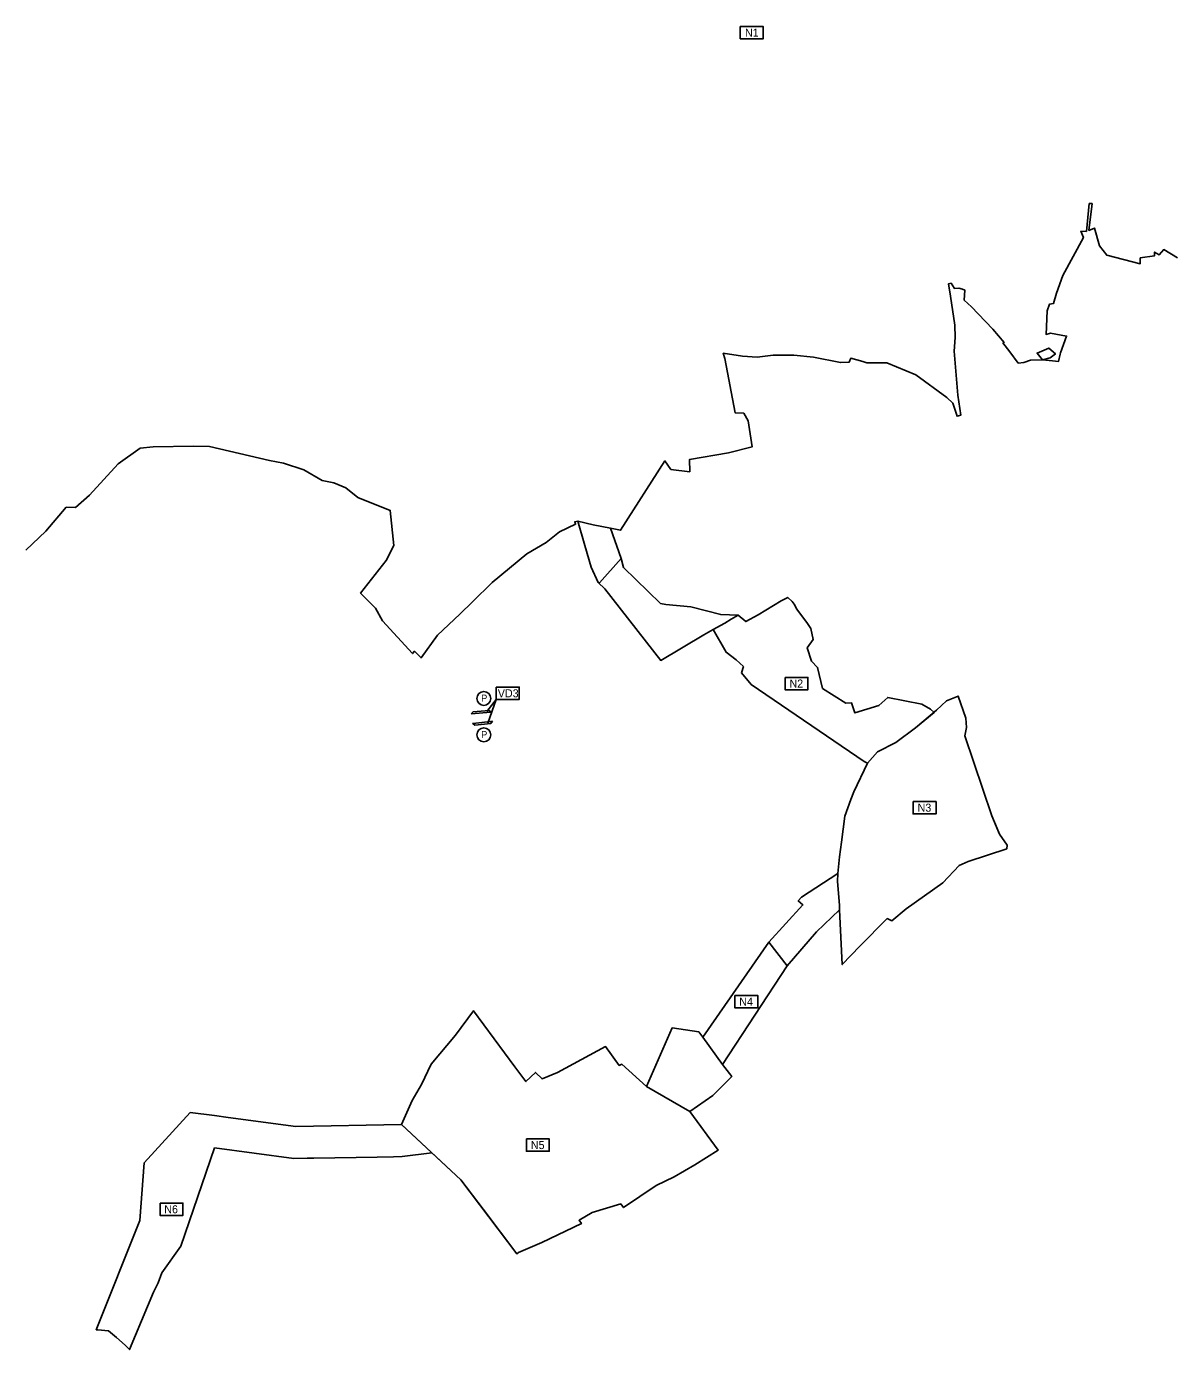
# Model space of a CAD drawing. Extents: x -547623 to -530360, y -1095798 to -1086523.
# Drawn here: x -546194 to -544764, y -1095798 to -1094145 of the extents above; entities that cross this region are included whole.
import ezdxf

# ---------------------------------------------------------------- set-up
doc = ezdxf.new("R2010")
doc.units = 0
for name, color, linetype in [('Vrstva 2', 7, 'Continuous'), ('Vrstva 27', 7, 'Continuous'), ('Vrstva 28', 7, 'Continuous'), ('Vrstva 29', 7, 'Continuous'), ('Vrstva 32', 7, 'Continuous'), ('Vrstva 36', 7, 'Continuous'), ('Vrstva 73', 7, 'Continuous')]:
    doc.layers.add(name, color=color, linetype=linetype)

msp = doc.modelspace()

# ---------------------------------------------------------------- linework, layer by layer
at = {"layer": 'Vrstva 2'}
for q in [(-545618.4, -1095001), (-545617.1, -1095015.3)]:
    msp.add_line((-545606.7, -1094985.8), q, dxfattribs=at)
msp.add_lwpolyline([(-545606.7, -1094970.3), (-545578, -1094970.3), (-545578, -1094985.8), (-545606.7, -1094985.8)], close=True, dxfattribs=at)
at = {"layer": 'Vrstva 27'}
msp.add_lwpolyline([(-546194.3, -1094799.4), (-546169.5, -1094775.5), (-546144.1, -1094745.5), (-546132.4, -1094746.2), (-546115, -1094730.6), (-546079, -1094691.6), (-546051.5, -1094672), (-546035.4, -1094670.2), (-545984.8, -1094669.3), (-545965, -1094669.6), (-545889.9, -1094687.2), (-545872.5, -1094690.6), (-545847.3, -1094699.1), (-545824.3, -1094712.4), (-545809.7, -1094715.1), (-545794.8, -1094721.6), (-545779.8, -1094733.3), (-545739.1, -1094749.6), (-545734.6, -1094793.4), (-545744.1, -1094812.1), (-545776.1, -1094853.2), (-545757.5, -1094871.9), (-545748.7, -1094887.7), (-545711.5, -1094928.4), (-545708.9, -1094925.6), (-545700.5, -1094933.9), (-545680, -1094905.5), (-545652, -1094879.2), (-545636.5, -1094863.8), (-545611.7, -1094839.5), (-545568.6, -1094803.9), (-545544.4, -1094789.6), (-545527.8, -1094776.3), (-545507.6, -1094767), (-545508.6, -1094763.8), (-545504.7, -1094763), (-545485.5, -1094767.6), (-545463.9, -1094771.9), (-545451.2, -1094774.5), (-545395.9, -1094687.7), (-545388.4, -1094698.5), (-545364.8, -1094701.3), (-545365.1, -1094686), (-545316.5, -1094677.8), (-545286.7, -1094670.1), (-545291.7, -1094637.6), (-545297.3, -1094628.1), (-545308, -1094627.9), (-545321.1, -1094559.7), (-545322.9, -1094553.3), (-545298.8, -1094556.8), (-545280.4, -1094558.3), (-545260.8, -1094555.6), (-545234.9, -1094555.8), (-545210.4, -1094558.2), (-545176.6, -1094564.9), (-545165.6, -1094564.3), (-545163.6, -1094559.6), (-545148.6, -1094563.8), (-545143.4, -1094565.3), (-545118.4, -1094565.3), (-545082.5, -1094580.4), (-545043.5, -1094608.6), (-545036, -1094615.7), (-545030.7, -1094631.9), (-545026.2, -1094630.6), (-545030, -1094605.6), (-545034.6, -1094550.8), (-545033.3, -1094533.8), (-545033.5, -1094518.2), (-545039.1, -1094481.9), (-545041.3, -1094466.5), (-545038.3, -1094465.8), (-545034.1, -1094472.3), (-545028.6, -1094471.9), (-545024, -1094473.4), (-545021.1, -1094474.4), (-545021.8, -1094486.9), (-545012.8, -1094495.3), (-545004.3, -1094504.2), (-544986, -1094523.4), (-544972.1, -1094540), (-544973.6, -1094540.4), (-544964.9, -1094551.6), (-544954.3, -1094565.5), (-544947.3, -1094564.8), (-544938.9, -1094561.8), (-544924, -1094561.5), (-544930.9, -1094553.1), (-544916.2, -1094546.8), (-544908, -1094554.2), (-544914.3, -1094559.1), (-544924, -1094561.5), (-544911.7, -1094562.9), (-544904.2, -1094563.7), (-544902.1, -1094554.5), (-544901.5, -1094552.6), (-544893.9, -1094531.9), (-544913.9, -1094528.3), (-544919.6, -1094529.8), (-544918.4, -1094500.1), (-544915.1, -1094491.9), (-544910.3, -1094491.2), (-544906.4, -1094478.3), (-544898.7, -1094456.2), (-544873, -1094408.8), (-544876.1, -1094400.8), (-544869.2, -1094401.1), (-544865.7, -1094366.4), (-544862, -1094366.4), (-544866.1, -1094399.8), (-544859.1, -1094397), (-544853, -1094418.9), (-544843.8, -1094430.8), (-544801.9, -1094441.4), (-544801.8, -1094434.1), (-544784.2, -1094431.6), (-544783.9, -1094426.9), (-544778.4, -1094430.5), (-544772.6, -1094423.7), (-544755.4, -1094434.1)], dxfattribs=at)
at = {"layer": 'Vrstva 28'}
for p, q in [((-545958.7, -1095505.7), (-545989, -1095501.7)), ((-546052, -1095636.9), (-546106.6, -1095773.3)), ((-546024.4, -1095702.2), (-546000.8, -1095668.6)), ((-546029, -1095714.5), (-546024.4, -1095702.2)), ((-546035, -1095726.3), (-546029, -1095714.5))]:
    msp.add_line(p, q, dxfattribs=at)
for points in [[(-545485.5, -1094767.6), (-545504.7, -1094763), (-545496, -1094793.4), (-545488.2, -1094820.5), (-545479.4, -1094839.5)], [(-545450.7, -1094809.9), (-545463.9, -1094771.9), (-545485.5, -1094767.6)], [(-545304.5, -1094880.5), (-545326.2, -1094879.8), (-545363.5, -1094870.2), (-545394.6, -1094867.1), (-545401.5, -1094865.8), (-545447.7, -1094820.9), (-545450.7, -1094809.9)], [(-545479.4, -1094839.5), (-545471.1, -1094847.8), (-545401.1, -1094937.1), (-545347.4, -1094905.2), (-545335.4, -1094898.4)], [(-545335.4, -1094898.4), (-545319.4, -1094926.9), (-545307, -1094936.2), (-545297.8, -1094944.6), (-545300.1, -1094952.7), (-545288, -1094967.2), (-545146.7, -1095063.3), (-545142.8, -1095065.2), (-545136.3, -1095058.2), (-545130.2, -1095051.2), (-545107.3, -1095039.6), (-545082.9, -1095021.3), (-545059.6, -1095001.9), (-545064, -1094997.8), (-545074.9, -1094991.6), (-545117.4, -1094983.3), (-545128.4, -1094993.3), (-545158.4, -1095002.7), (-545162.6, -1094990.2), (-545169.8, -1094990.4), (-545198.8, -1094972.1), (-545205.2, -1094945.7), (-545212.7, -1094937.8), (-545218.2, -1094921.3), (-545210.7, -1094910.9), (-545213.4, -1094897.3), (-545217.9, -1094891), (-545231, -1094872.8), (-545234.5, -1094866.7), (-545236.8, -1094863.5), (-545242.3, -1094858.3), (-545250.8, -1094862.5), (-545279.4, -1094880.1), (-545294.7, -1094888.6), (-545304.5, -1094880.5)], [(-545243.2, -1095318.4), (-545206.5, -1095275.9), (-545177.7, -1095248.6), (-545177.8, -1095242.9), (-545180.4, -1095213.2), (-545179.7, -1095203.4), (-545225.3, -1095232.6), (-545229.3, -1095237.4), (-545223.5, -1095242.4), (-545265.9, -1095289.1)], [(-545265.9, -1095289.1), (-545348.7, -1095407.7)], [(-545324, -1095441.7), (-545243.2, -1095318.4)], [(-545348.7, -1095407.7), (-545353.6, -1095400.9), (-545386.7, -1095396), (-545418.8, -1095469.4), (-545364.9, -1095500.4), (-545336.2, -1095480.7), (-545312.4, -1095457), (-545324, -1095441.7)], [(-545989, -1095501.7), (-546046.7, -1095564.7), (-546052, -1095636.9)], [(-545941.5, -1095508), (-545958.7, -1095505.7)], [(-545725, -1095516.9), (-545857.1, -1095519.2), (-545941.5, -1095508)], [(-545734.9, -1095557.1), (-545724.3, -1095556.9), (-545687.2, -1095552), (-545725, -1095516.9)], [(-546000.8, -1095668.6), (-545958.7, -1095546.1)], [(-545958.7, -1095546.1), (-545859.4, -1095559.2), (-545842.8, -1095558.9), (-545834.7, -1095558.8), (-545755.5, -1095557.4)], [(-545755.5, -1095557.4), (-545734.9, -1095557.1)], [(-546106.6, -1095773.3), (-546104.7, -1095773.2), (-546091.3, -1095774.5), (-546081.4, -1095783), (-546070.4, -1095792.5), (-546064.8, -1095797.9), (-546035, -1095726.3)]]:
    msp.add_lwpolyline(points, dxfattribs=at)
at = {"layer": 'Vrstva 29'}
for points in [[(-545637.8, -1095003.7), (-545613.4, -1095001.6), (-545613.1, -1095001.6), (-545615.7, -1094999.4), (-545635.6, -1095001.2), (-545637.8, -1095003.7)], [(-545611.3, -1095013.1), (-545613.8, -1095013.4), (-545636.1, -1095015.8), (-545633.4, -1095018.1), (-545613.5, -1095015.9), (-545611.3, -1095013.1)]]:
    msp.add_lwpolyline(points, dxfattribs=at)
for centre in [(-545622.2, -1094984.5), (-545622.2, -1095029.9)]:
    msp.add_circle(centre, 8.68, dxfattribs=at)
at = {"layer": 'Vrstva 32'}
for points in [[(-545016.9, -1095188.3), (-544968.8, -1095172.4), (-544968.4, -1095167.9), (-544977.6, -1095154), (-544987.5, -1095131.1), (-545021.1, -1095031.3), (-545019.2, -1095020.9), (-545019.9, -1095009.1), (-545029.6, -1094981.6), (-545043.9, -1094987.4), (-545056.3, -1094999.1), (-545082.9, -1095021.3), (-545107.3, -1095039.6), (-545130.2, -1095051.2), (-545136.3, -1095058.2), (-545142.8, -1095065.2), (-545159.6, -1095101.2), (-545163.6, -1095110.7), (-545171.2, -1095131.7), (-545175.2, -1095164.2), (-545177.8, -1095182.3), (-545179.7, -1095203.4), (-545180.4, -1095213.2), (-545177.8, -1095242.9), (-545177.7, -1095248.6), (-545174.3, -1095317.1), (-545152.4, -1095294.1), (-545118.3, -1095259.6), (-545112.3, -1095262.2), (-545094.5, -1095247.2), (-545048.7, -1095215), (-545028.2, -1095193.2), (-545016.9, -1095188.3)], [(-545569.5, -1095463.1), (-545583.4, -1095444.8), (-545635, -1095374.7), (-545657.5, -1095405.2), (-545687.8, -1095441.4), (-545700, -1095466.8), (-545711.6, -1095487), (-545725, -1095516.9)], [(-545329.2, -1095548.8), (-545364.9, -1095500.4), (-545418.8, -1095469.4), (-545449.8, -1095441.6), (-545453, -1095443), (-545470.1, -1095419.5), (-545530, -1095451.9), (-545549.3, -1095459.9), (-545557.6, -1095451.8), (-545569.5, -1095463.1)], [(-545725, -1095516.9), (-545650.8, -1095585.9), (-545580.8, -1095678.4), (-545578.7, -1095676.9), (-545549.5, -1095664.4), (-545500.2, -1095640.5), (-545503.2, -1095636.4), (-545487, -1095626.7), (-545451, -1095616.1)], [(-545451, -1095616.1), (-545447.6, -1095620.6), (-545406.9, -1095593), (-545384.2, -1095582.2), (-545358.6, -1095567.2), (-545329.2, -1095548.8)]]:
    msp.add_lwpolyline(points, dxfattribs=at)
at = {"layer": 'Vrstva 36'}
for points in [[(-545301.7, -1094145.1), (-545273.1, -1094145.1), (-545273.1, -1094160.5), (-545301.7, -1094160.5)], [(-545245.7, -1094958.2), (-545217.1, -1094958.2), (-545217.1, -1094973.7), (-545245.7, -1094973.7)], [(-545085.7, -1095113.3), (-545057.1, -1095113.3), (-545057.1, -1095128.7), (-545085.7, -1095128.7)], [(-545308.4, -1095355.6), (-545279.8, -1095355.6), (-545279.8, -1095371.1), (-545308.4, -1095371.1)], [(-545569, -1095534.8), (-545540.4, -1095534.8), (-545540.4, -1095550.2), (-545569, -1095550.2)], [(-546026.8, -1095614.9), (-545998.2, -1095614.9), (-545998.2, -1095630.4), (-546026.8, -1095630.4)]]:
    msp.add_lwpolyline(points, close=True, dxfattribs=at)
at = {"layer": 'Vrstva 73'}
for points in [[(-546194.3, -1094799.4), (-546169.5, -1094775.5), (-546144.1, -1094745.5), (-546132.4, -1094746.2), (-546115, -1094730.6), (-546079, -1094691.6), (-546051.5, -1094672), (-546035.4, -1094670.2), (-545984.8, -1094669.3), (-545965, -1094669.6), (-545889.9, -1094687.2), (-545872.5, -1094690.6), (-545847.3, -1094699.1), (-545824.3, -1094712.4), (-545809.7, -1094715.1), (-545794.8, -1094721.6), (-545779.8, -1094733.3), (-545739.1, -1094749.6), (-545734.6, -1094793.4), (-545744.1, -1094812.1), (-545776.1, -1094853.2), (-545757.5, -1094871.9), (-545748.7, -1094887.7), (-545711.5, -1094928.4), (-545708.9, -1094925.6), (-545700.5, -1094933.9), (-545680, -1094905.5), (-545652, -1094879.2), (-545636.5, -1094863.8), (-545611.7, -1094839.5), (-545568.6, -1094803.9), (-545544.4, -1094789.6), (-545527.8, -1094776.3), (-545507.6, -1094767), (-545508.6, -1094763.8), (-545504.7, -1094763), (-545485.5, -1094767.6), (-545463.9, -1094771.9), (-545451.2, -1094774.5), (-545395.9, -1094687.7), (-545388.4, -1094698.5), (-545364.8, -1094701.3), (-545365.1, -1094686), (-545316.5, -1094677.8), (-545286.7, -1094670.1), (-545291.7, -1094637.6), (-545297.3, -1094628.1), (-545308, -1094627.9), (-545321.1, -1094559.7), (-545322.9, -1094553.3), (-545298.8, -1094556.8), (-545280.4, -1094558.3), (-545260.8, -1094555.6), (-545234.9, -1094555.8), (-545210.4, -1094558.2), (-545176.6, -1094564.9), (-545165.6, -1094564.3), (-545163.6, -1094559.6), (-545148.6, -1094563.8), (-545143.4, -1094565.3), (-545118.4, -1094565.3), (-545082.5, -1094580.4), (-545043.5, -1094608.6), (-545036, -1094615.7), (-545030.7, -1094631.9), (-545026.2, -1094630.6), (-545030, -1094605.6), (-545034.6, -1094550.8), (-545033.3, -1094533.8), (-545033.5, -1094518.2), (-545039.1, -1094481.9), (-545041.3, -1094466.5), (-545038.3, -1094465.8), (-545034.1, -1094472.3), (-545028.6, -1094471.9), (-545024, -1094473.4), (-545021.1, -1094474.4), (-545021.8, -1094486.9), (-545012.8, -1094495.3), (-545004.3, -1094504.2), (-544986, -1094523.4), (-544972.1, -1094540), (-544973.6, -1094540.4), (-544964.9, -1094551.6), (-544954.3, -1094565.5), (-544947.3, -1094564.8), (-544938.9, -1094561.8), (-544924, -1094561.5), (-544930.9, -1094553.1), (-544916.2, -1094546.8), (-544908, -1094554.2), (-544914.3, -1094559.1), (-544924, -1094561.5), (-544911.7, -1094562.9), (-544904.2, -1094563.7), (-544902.1, -1094554.5), (-544901.5, -1094552.6), (-544893.9, -1094531.9), (-544913.9, -1094528.3), (-544919.6, -1094529.8), (-544918.4, -1094500.1), (-544915.1, -1094491.9), (-544910.3, -1094491.2), (-544906.4, -1094478.3), (-544898.7, -1094456.2), (-544873, -1094408.8), (-544876.1, -1094400.8), (-544869.2, -1094401.1), (-544865.7, -1094366.4), (-544862, -1094366.4), (-544866.1, -1094399.8), (-544859.1, -1094397), (-544853, -1094418.9), (-544843.8, -1094430.8), (-544801.9, -1094441.4), (-544801.8, -1094434.1), (-544784.2, -1094431.6), (-544783.9, -1094426.9), (-544778.4, -1094430.5), (-544772.6, -1094423.7), (-544755.4, -1094434.1)], [(-545450.7, -1094809.9), (-545463.9, -1094771.9), (-545485.5, -1094767.6), (-545504.7, -1094763), (-545496, -1094793.4), (-545488.2, -1094820.5), (-545479.4, -1094839.5), (-545477.6, -1094840.2), (-545450.7, -1094809.9)], [(-545321.2, -1094890.5), (-545313.1, -1094885.7), (-545304.5, -1094880.5), (-545326.2, -1094879.8), (-545363.5, -1094870.2), (-545394.6, -1094867.1), (-545401.5, -1094865.8), (-545447.7, -1094820.9), (-545450.7, -1094809.9), (-545477.6, -1094840.2), (-545479.4, -1094839.5), (-545471.1, -1094847.8), (-545401.1, -1094937.1), (-545347.4, -1094905.2), (-545335.4, -1094898.4), (-545321.2, -1094890.5)], [(-545294.7, -1094888.6), (-545304.5, -1094880.5), (-545313.1, -1094885.7), (-545321.2, -1094890.5), (-545335.4, -1094898.4), (-545319.4, -1094926.9), (-545307, -1094936.2), (-545297.8, -1094944.6), (-545300.1, -1094952.7), (-545288, -1094967.2), (-545146.7, -1095063.3), (-545142.8, -1095065.2), (-545136.3, -1095058.2), (-545130.2, -1095051.2), (-545107.3, -1095039.6), (-545082.9, -1095021.3), (-545059.6, -1095001.9), (-545064, -1094997.8), (-545074.9, -1094991.6), (-545117.4, -1094983.3), (-545128.4, -1094993.3), (-545158.4, -1095002.7), (-545162.6, -1094990.2), (-545169.8, -1094990.4), (-545198.8, -1094972.1), (-545205.2, -1094945.7), (-545212.7, -1094937.8), (-545218.2, -1094921.3), (-545210.7, -1094910.9), (-545213.4, -1094897.3), (-545217.9, -1094891), (-545231, -1094872.8), (-545234.5, -1094866.7), (-545236.8, -1094863.5), (-545242.3, -1094858.3), (-545250.8, -1094862.5), (-545279.4, -1094880.1), (-545294.7, -1094888.6)], [(-544980.6, -1095146.9), (-544987.5, -1095131.1), (-545021.1, -1095031.3), (-545019.2, -1095020.9), (-545019.9, -1095009.1), (-545029.6, -1094981.6), (-545043.9, -1094987.4), (-545056.3, -1094999.1), (-545059.6, -1095001.9), (-545082.9, -1095021.3), (-545107.3, -1095039.6), (-545130.2, -1095051.2), (-545136.3, -1095058.2), (-545142.8, -1095065.2), (-545159.6, -1095101.2), (-545163.6, -1095110.7), (-545171.2, -1095131.7), (-545175.2, -1095164.2), (-545177.8, -1095182.3), (-545179.7, -1095203.4), (-545180.4, -1095213.2), (-545177.8, -1095242.9), (-545177.7, -1095248.6), (-545174.3, -1095317.1), (-545152.4, -1095294.1), (-545118.3, -1095259.6), (-545112.3, -1095262.2), (-545094.5, -1095247.2), (-545048.7, -1095215), (-545028.2, -1095193.2), (-545016.9, -1095188.3), (-544968.8, -1095172.4), (-544968.4, -1095167.9), (-544977.6, -1095154), (-544980.6, -1095146.9)], [(-545223.5, -1095242.4), (-545265.9, -1095289.1), (-545243.2, -1095318.4), (-545206.5, -1095275.9), (-545177.7, -1095248.6), (-545177.8, -1095242.9), (-545180.4, -1095213.2), (-545179.7, -1095203.4), (-545225.3, -1095232.6), (-545229.3, -1095237.4), (-545223.5, -1095242.4)], [(-545348.7, -1095407.7), (-545324, -1095441.7), (-545243.2, -1095318.4), (-545265.9, -1095289.1), (-545348.7, -1095407.7)], [(-545623.1, -1095622.6), (-545580.8, -1095678.4), (-545578.7, -1095676.9), (-545549.5, -1095664.4), (-545500.2, -1095640.5), (-545503.2, -1095636.4), (-545487, -1095626.7), (-545451, -1095616.1), (-545447.6, -1095620.6), (-545406.9, -1095593), (-545384.2, -1095582.2), (-545358.6, -1095567.2), (-545329.2, -1095548.8), (-545364.9, -1095500.4), (-545418.8, -1095469.4), (-545449.8, -1095441.6), (-545453, -1095443), (-545470.1, -1095419.5), (-545530, -1095451.9), (-545549.3, -1095459.9), (-545557.6, -1095451.8), (-545569.5, -1095463.1), (-545583.4, -1095444.8), (-545635, -1095374.7), (-545657.5, -1095405.2), (-545687.8, -1095441.4), (-545700, -1095466.8)], [(-545312.4, -1095457), (-545324, -1095441.7), (-545348.7, -1095407.7), (-545353.6, -1095400.9), (-545386.7, -1095396), (-545418.8, -1095469.4), (-545364.9, -1095500.4), (-545336.2, -1095480.7), (-545312.4, -1095457)], [(-545700, -1095466.8), (-545711.6, -1095487), (-545725, -1095516.9), (-545687.2, -1095552)], [(-545857.1, -1095519.2), (-545941.5, -1095508), (-545958.7, -1095505.7), (-545989, -1095501.7), (-546046.7, -1095564.7), (-546052, -1095636.9), (-546106.6, -1095773.3), (-546104.7, -1095773.2), (-546091.3, -1095774.5), (-546081.4, -1095783), (-546070.4, -1095792.5), (-546064.8, -1095797.9), (-546035, -1095726.3), (-546029, -1095714.5), (-546024.4, -1095702.2), (-546000.8, -1095668.6), (-545958.7, -1095546.1), (-545859.4, -1095559.2), (-545842.8, -1095558.9), (-545834.7, -1095558.8), (-545755.5, -1095557.4), (-545734.9, -1095557.1), (-545724.3, -1095556.9), (-545687.2, -1095552), (-545725, -1095516.9), (-545857.1, -1095519.2)], [(-545687.2, -1095552), (-545650.8, -1095585.9)], [(-545650.8, -1095585.9), (-545623.1, -1095622.6)]]:
    msp.add_lwpolyline(points, dxfattribs=at)

# ---------------------------------------------------------------- texts
at = {"layer": 'Vrstva 2'}
msp.add_text('VD3', height=10, dxfattribs=at).set_placement((-545604.7, -1094983.1))
at = {"layer": 'Vrstva 29'}
for p in [(-545625.6, -1094988.6), (-545625.6, -1095034)]:
    msp.add_text('P', height=8.75, dxfattribs=at).set_placement(p)
at = {"layer": 'Vrstva 36'}
for s, p in [('N1', (-545295.8, -1094157.8)), ('N2', (-545240.2, -1094970.9)), ('N3', (-545080.1, -1095126)), ('N4', (-545303, -1095368.4)), ('N5', (-545563.4, -1095547.5)), ('N6', (-546021.5, -1095627.7))]:
    msp.add_text(s, height=10, dxfattribs=at).set_placement(p)

doc.saveas('drawing.dxf')
